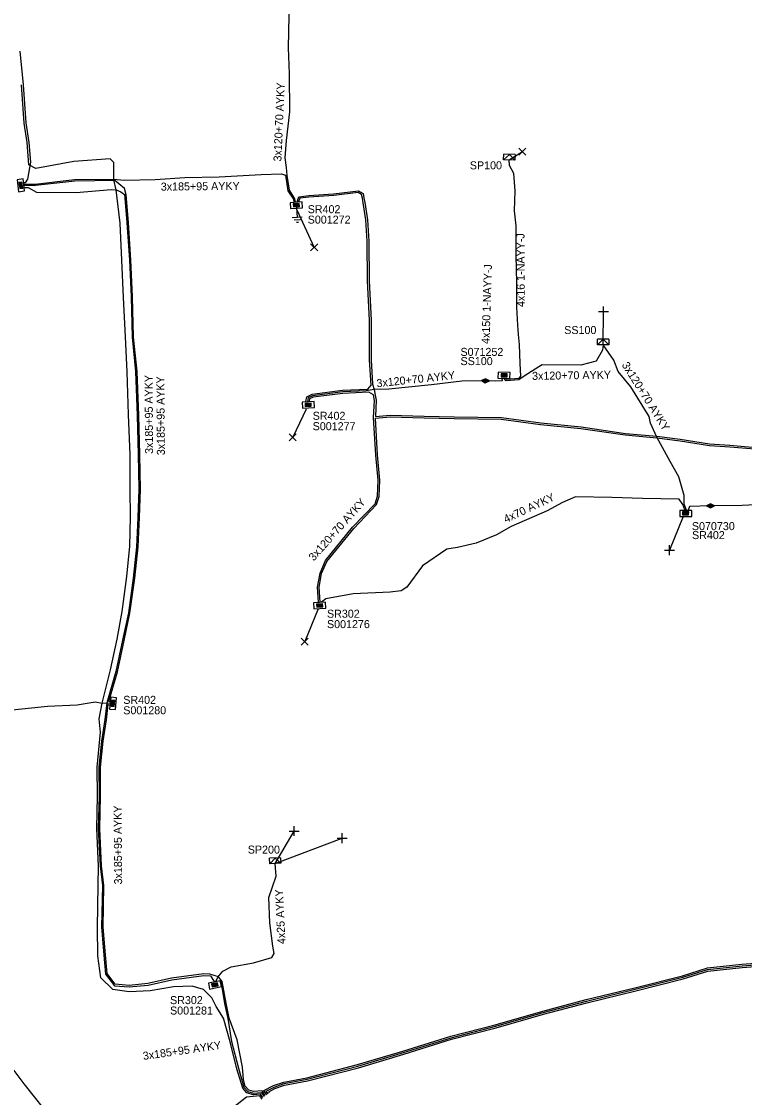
# Model space of a CAD drawing. Extents: x -763093 to -760976, y -1155572 to -1152009.
# Drawn here: x -762630 to -762539.8, y -1154689.2 to -1154554.8 of the extents above; entities that cross this region are included whole.
import ezdxf

# ---------------------------------------------------------------- set-up
doc = ezdxf.new("R2010")
doc.units = 0
for name, color, linetype in [('Vrstva 1', 7, 'Continuous'), ('Vrstva 14', 7, 'Continuous'), ('Vrstva 15', 7, 'Continuous'), ('Vrstva 19', 7, 'Continuous'), ('Vrstva 28', 7, 'Continuous'), ('Vrstva 29', 7, 'Continuous'), ('Vrstva 30', 7, 'Continuous'), ('Vrstva 31', 7, 'Continuous'), ('Vrstva 33', 7, 'Continuous'), ('Vrstva 34', 7, 'Continuous'), ('Vrstva 4', 7, 'Continuous'), ('Vrstva 5', 7, 'Continuous'), ('Vrstva 52', 7, 'Continuous'), ('Vrstva 54', 7, 'Continuous'), ('Vrstva 59', 7, 'Continuous'), ('Vrstva 6', 7, 'Continuous'), ('Vrstva 8', 7, 'Continuous'), ('Vrstva 9', 7, 'Continuous')]:
    doc.layers.add(name, color=color, linetype=linetype)

# ---------------------------------------------------------------- blocks, each defined once
blk = doc.blocks.new('NN870')
at = {"layer": 'Vrstva 4'}
for points in [[(0, -0.25), (0.5, 0), (0, 0.25), (-0.5, 0), (0, -0.25)], [(0.37, 0), (0, 0.19), (-0.36, 0), (0, -0.19), (0.37, 0)], [(0.24, 0), (0, 0.12), (-0.25, 0), (0, -0.12), (0.24, 0)], [(0.12, 0), (0, 0.06), (-0.13, 0), (0, -0.06), (0.12, 0)]]:
    blk.add_lwpolyline(points, dxfattribs=at)
blk = doc.blocks.new('NN800')
at = {"layer": 'Vrstva 1'}
for points in [[(-0.44, 0.44), (0.44, -0.44)], [(-0.44, -0.44), (0.44, 0.44)]]:
    blk.add_lwpolyline(points, dxfattribs=at)
blk = doc.blocks.new('NN620')
at = {"layer": 'Vrstva 8'}
for points in [[(0.75, 0), (-0.75, 0)], [(-0.75, 0), (-0.75, -0.75)], [(0.75, -0.75), (0.75, 0)], [(-0.75, -0.75), (0.75, -0.75)], [(0.37, -0.18), (-0.38, -0.18)], [(-0.38, -0.18), (-0.38, -0.56)], [(-0.38, -0.56), (0.37, -0.56)], [(0.32, -0.23), (-0.33, -0.23)], [(-0.33, -0.23), (-0.33, -0.51)], [(-0.33, -0.51), (0.32, -0.51)], [(0.27, -0.27), (-0.28, -0.27)], [(-0.28, -0.27), (-0.28, -0.46)], [(-0.28, -0.46), (0.27, -0.46)], [(0.23, -0.32), (-0.23, -0.32)], [(-0.23, -0.32), (-0.23, -0.42)], [(-0.23, -0.42), (0.23, -0.42)], [(-0.19, -0.37), (0.19, -0.37)], [(0.23, -0.42), (0.23, -0.32)], [(0.27, -0.46), (0.27, -0.27)], [(0.32, -0.51), (0.32, -0.23)], [(0.37, -0.56), (0.37, -0.18)]]:
    blk.add_lwpolyline(points, dxfattribs=at)
blk = doc.blocks.new('NN630')
at = {"layer": 'Vrstva 9'}
for points in [[(0, -0.7), (-0.7, 0)], [(-0.7, -0.7), (-0.7, 0), (0.7, 0), (0.7, -0.7)], [(-0.7, -0.7), (0.7, -0.7)], [(0, -0.7), (0.7, 0)]]:
    blk.add_lwpolyline(points, dxfattribs=at)
blk = doc.blocks.new('NN810')
at = {"layer": 'Vrstva 14'}
for points in [[(0, -0.64), (0, -1.89)], [(0.63, -1.89), (-0.62, -1.89)], [(0.39, -2.2), (-0.4, -2.2)], [(0, -2.52), (-0.12, -2.52)], [(0.14, -2.52), (0, -2.52)]]:
    blk.add_lwpolyline(points, dxfattribs=at)

msp = doc.modelspace()

# ---------------------------------------------------------------- linework, layer by layer
at = {"layer": 'Vrstva 5'}
for points in [[(-762595.83, -1154577.36), (-762595.94, -1154576.91), (-762596.59, -1154575.89), (-762596.86, -1154574.08), (-762596.96, -1154573.09), (-762597.12, -1154571.85), (-762596.95, -1154569.71), (-762596.52, -1154566.13), (-762596.58, -1154561.37), (-762596.7, -1154558.13), (-762596.63, -1154554.1), (-762596.69, -1154552.42), (-762596.12, -1154549.48), (-762594.77, -1154547.62), (-762592.4, -1154546.5)], [(-762630.26, -1154558.56), (-762629.86, -1154562.74), (-762629.51, -1154567.5), (-762629.15, -1154569.95), (-762628.94, -1154572.41), (-762629.3, -1154574.53), (-762629.59, -1154574.98), (-762629.73, -1154574.99)], [(-762599.91, -1154689.21), (-762600.2, -1154688.79), (-762601.1, -1154688.88), (-762601.89, -1154688.63), (-762602.42, -1154688.05), (-762603.16, -1154685.63), (-762604.01, -1154682.26), (-762604.82, -1154679.31), (-762605.75, -1154677.86), (-762606.27, -1154676.79), (-762607.3, -1154675.75), (-762608.73, -1154675.33), (-762611.06, -1154675.42), (-762613.97, -1154675.92), (-762616.61, -1154676.03), (-762618.64, -1154675.73), (-762620.16, -1154674.27), (-762620.52, -1154671.52), (-762620.55, -1154667.97), (-762620.48, -1154662.72), (-762620.44, -1154660.31), (-762620.66, -1154655.62), (-762620.57, -1154651.6), (-762620.6, -1154647.96), (-762620.19, -1154643.58), (-762620.36, -1154641.94), (-762619.96, -1154639.97), (-762618.92, -1154635.82), (-762618.12, -1154631.96), (-762617.49, -1154628.54), (-762616.9, -1154624.17), (-762616.53, -1154620.36), (-762616.44, -1154616.74), (-762616.48, -1154613.25), (-762616.49, -1154608.94), (-762616.67, -1154603.92), (-762616.84, -1154598.6), (-762617.06, -1154594.22), (-762617.31, -1154589.29), (-762617.51, -1154584.64), (-762617.73, -1154580.02), (-762618.22, -1154575.86), (-762618.51, -1154574.61), (-762618.53, -1154572.44), (-762618.97, -1154571.99), (-762623.51, -1154572.32), (-762628.25, -1154573.21), (-762629.12, -1154572.75), (-762629.35, -1154569.97), (-762629.71, -1154567.52), (-762630.06, -1154562.76)], [(-762629.72, -1154575.15), (-762628.34, -1154575.14), (-762623.41, -1154574.57), (-762618.51, -1154574.51), (-762617.23, -1154574.66), (-762613.36, -1154574.56), (-762609.67, -1154574.33), (-762605.36, -1154574.24), (-762600.12, -1154573.96), (-762597.57, -1154573.86), (-762597.07, -1154574.05), (-762596.79, -1154575.97), (-762596.1, -1154577.01), (-762596.03, -1154577.39)], [(-762619, -1154639.76), (-762619.14, -1154639.76), (-762618.08, -1154636.04), (-762617.23, -1154632.15), (-762616.5, -1154628.72), (-762615.91, -1154624.38), (-762615.5, -1154620.45), (-762615.32, -1154616.78), (-762615.2, -1154613.24), (-762615.29, -1154608.92), (-762615.4, -1154604.04), (-762615.62, -1154598.55), (-762616.06, -1154594.25), (-762616.17, -1154589.22), (-762616.38, -1154584.61), (-762616.69, -1154579.94), (-762616.96, -1154576.49), (-762617.19, -1154575.69), (-762617.88, -1154575.1), (-762618.38, -1154574.71), (-762623.39, -1154574.77), (-762628.32, -1154575.34), (-762629.7, -1154575.35)], [(-762629.67, -1154575.55), (-762629.21, -1154575.56), (-762628.18, -1154576.15), (-762623.22, -1154576.18), (-762618.86, -1154575.8), (-762618.22, -1154575.86), (-762617.64, -1154576.12), (-762617.17, -1154576.43), (-762616.89, -1154579.96), (-762616.58, -1154584.63), (-762616.37, -1154589.22), (-762616.23, -1154594.25), (-762615.82, -1154598.57), (-762615.6, -1154604.04), (-762615.49, -1154608.92), (-762615.4, -1154613.24), (-762615.52, -1154616.78), (-762615.67, -1154620.45), (-762616.11, -1154624.36), (-762616.7, -1154628.68), (-762617.43, -1154632.11), (-762618.28, -1154636), (-762619.4, -1154639.94), (-762619.65, -1154642.01), (-762620.07, -1154644.7), (-762620.4, -1154647.97), (-762620.37, -1154651.6), (-762620.46, -1154655.62), (-762620.24, -1154660.3), (-762619.95, -1154662.75), (-762620.06, -1154667.93), (-762619.75, -1154671.43), (-762619.57, -1154673.82), (-762618.45, -1154675.28), (-762616.59, -1154675.42), (-762614.22, -1154675.2), (-762611.28, -1154674.51), (-762607.29, -1154673.97), (-762606.45, -1154674.04), (-762606, -1154674.72)], [(-762595.64, -1154577.36), (-762595.43, -1154576.74), (-762594.18, -1154576.57), (-762591.08, -1154576.37), (-762587.97, -1154576), (-762587.4, -1154576.3), (-762587.28, -1154576.88), (-762587.17, -1154577.46), (-762586.85, -1154579.59), (-762586.68, -1154582.29), (-762586.62, -1154587.23), (-762586.39, -1154592.12), (-762586.4, -1154597.09), (-762586.2, -1154600.12), (-762586.02, -1154600.78), (-762585.88, -1154601.49), (-762585.76, -1154602.14), (-762585.86, -1154604.18), (-762584.02, -1154604.01), (-762579.76, -1154604.13), (-762576.01, -1154604.2), (-762570.12, -1154604.3), (-762565.21, -1154604.96), (-762560.16, -1154605.48), (-762554.63, -1154606.28), (-762550.7, -1154606.64), (-762547.79, -1154607.02), (-762544.13, -1154607.59), (-762541.57, -1154607.77), (-762537.41, -1154608.11)], [(-762594.53, -1154602.29), (-762594.43, -1154601.71), (-762593.76, -1154601.38), (-762589.95, -1154600.89), (-762586.81, -1154600.74), (-762586.39, -1154600.24), (-762586.6, -1154597.09), (-762586.59, -1154592.12), (-762586.82, -1154587.23), (-762586.88, -1154582.29), (-762587.05, -1154579.61), (-762587.37, -1154577.5), (-762587.48, -1154576.92), (-762587.58, -1154576.44), (-762588.01, -1154576.2), (-762591.06, -1154576.57), (-762594.16, -1154576.77), (-762595.31, -1154576.92), (-762595.45, -1154577.36)], [(-762547.01, -1154615.87), (-762547.28, -1154615.11), (-762547.31, -1154614.03), (-762547.97, -1154611.72), (-762549.05, -1154609.79), (-762550.71, -1154606.74), (-762551.49, -1154604.99), (-762551.66, -1154604.16), (-762553.97, -1154600.48), (-762555.54, -1154598.55), (-762556.07, -1154597.15), (-762557.41, -1154595.22), (-762557.51, -1154595.87), (-762558.3, -1154597.26), (-762560.2, -1154597.77), (-762565.03, -1154597.72), (-762565.44, -1154597.96), (-762567.26, -1154599.13), (-762567.92, -1154599.57), (-762569.53, -1154599.72), (-762569.79, -1154599.41)], [(-762572.12, -1154599.71), (-762575.05, -1154599.77), (-762578.86, -1154600.22), (-762584.19, -1154600.75), (-762586.02, -1154600.78), (-762586.99, -1154600.95), (-762589.93, -1154601.09), (-762593.7, -1154601.57), (-762594.25, -1154601.84), (-762594.33, -1154602.29)], [(-762570.07, -1154599.41), (-762570.03, -1154599.7), (-762570.81, -1154599.75), (-762572.12, -1154599.71)], [(-762592.94, -1154627.35), (-762593.07, -1154625.48), (-762592.77, -1154623.72), (-762592.08, -1154622.17), (-762588.7, -1154618), (-762585.9, -1154615.06), (-762585.58, -1154614.12), (-762585.51, -1154612.14), (-762585.8, -1154608.98), (-762586.07, -1154604.29), (-762585.96, -1154602.16), (-762586.09, -1154601.45), (-762586.66, -1154601.13), (-762589.91, -1154601.29), (-762593.64, -1154601.76), (-762594.07, -1154601.97), (-762594.12, -1154602.28)], [(-762592.74, -1154627.35), (-762592.87, -1154625.5), (-762592.57, -1154623.78), (-762591.9, -1154622.27), (-762588.54, -1154618.14), (-762585.72, -1154615.16), (-762585.38, -1154614.16), (-762585.31, -1154612.14), (-762585.6, -1154608.96), (-762585.86, -1154604.38), (-762584.02, -1154604.21), (-762579.76, -1154604.33), (-762576.01, -1154604.4), (-762570.14, -1154604.5), (-762565.23, -1154605.16), (-762560.18, -1154605.68), (-762554.65, -1154606.48), (-762550.72, -1154606.84), (-762547.81, -1154607.22), (-762544.15, -1154607.79), (-762541.59, -1154607.97), (-762537.43, -1154608.31)], [(-762547.23, -1154615.84), (-762547.46, -1154615.17), (-762547.9, -1154614.48), (-762552.51, -1154614.4), (-762556.31, -1154614.29), (-762560.87, -1154614.2), (-762562.5, -1154614.91), (-762564.4, -1154615.97), (-762568.88, -1154617.9), (-762570.75, -1154618.94), (-762573.27, -1154620), (-762575.62, -1154620.55), (-762576.95, -1154620.74), (-762579.96, -1154622.84), (-762581.91, -1154625.49), (-762582.62, -1154625.96), (-762584, -1154626.11), (-762588.65, -1154626.31), (-762592.06, -1154626.93), (-762592.59, -1154627.34)], [(-762503.87, -1154616.15), (-762504.09, -1154615.27), (-762506.42, -1154615.21), (-762510.1, -1154615.29), (-762514.01, -1154615.2), (-762517.37, -1154615.23), (-762522.56, -1154615.41), (-762527.8, -1154615.36), (-762531.54, -1154615.29), (-762535.89, -1154615.07), (-762540.05, -1154615.28), (-762544.02, -1154615.34), (-762546.63, -1154615.39), (-762546.79, -1154615.85)], [(-762632.02, -1154640.87), (-762626.81, -1154640.36), (-762623.09, -1154640.17), (-762620.87, -1154639.79), (-762619.96, -1154639.97), (-762619.3, -1154639.95), (-762619.02, -1154639.96)], [(-762599.6, -1154688.97), (-762600.01, -1154688.37), (-762601.06, -1154688.48), (-762601.67, -1154688.29), (-762602.12, -1154687.79), (-762602.34, -1154686.96), (-762602.43, -1154685.45), (-762603.13, -1154682.02), (-762604.1, -1154679.3), (-762604.48, -1154677.46), (-762604.97, -1154674.72), (-762605.46, -1154674.14), (-762606.51, -1154673.83), (-762607.29, -1154673.77), (-762611.32, -1154674.31), (-762614.26, -1154675), (-762616.59, -1154675.22), (-762618.35, -1154675.08), (-762619.37, -1154673.74), (-762619.55, -1154671.41), (-762619.86, -1154667.93), (-762619.75, -1154662.73), (-762620.04, -1154660.29), (-762620.26, -1154655.62), (-762620.17, -1154651.6), (-762620.2, -1154647.98), (-762619.87, -1154644.72), (-762619.45, -1154642.05), (-762619.22, -1154640.15), (-762619.05, -1154640.16)], [(-762605.77, -1154674.72), (-762605.54, -1154674.21), (-762604.91, -1154673.43), (-762603.88, -1154672.91), (-762601.07, -1154672.39), (-762598.79, -1154671.73), (-762598.51, -1154671.25), (-762598.66, -1154670.34), (-762599.02, -1154667.4), (-762599.15, -1154664.25), (-762598.26, -1154661.59), (-762598.35, -1154660.01)], [(-762599.42, -1154688.87), (-762599.77, -1154688.36), (-762598.56, -1154687.74), (-762597.3, -1154687.29), (-762594.4, -1154686.75), (-762588.08, -1154685.12), (-762582.41, -1154683.42), (-762576.45, -1154681.57), (-762570.88, -1154680.13), (-762564.94, -1154678.42), (-762559.54, -1154677), (-762553.45, -1154675.51), (-762547.51, -1154674.02), (-762544.4, -1154673.04), (-762540.08, -1154672.59), (-762537.32, -1154672.36)], [(-762599.25, -1154688.76), (-762599.48, -1154688.43), (-762598.48, -1154687.92), (-762597.25, -1154687.48), (-762594.36, -1154686.95), (-762588.03, -1154685.31), (-762582.35, -1154683.61), (-762576.4, -1154681.76), (-762570.83, -1154680.32), (-762564.89, -1154678.61), (-762559.49, -1154677.19), (-762553.4, -1154675.7), (-762547.46, -1154674.21), (-762544.36, -1154673.24), (-762540.06, -1154672.79), (-762537.31, -1154672.56)], [(-762599.09, -1154688.65), (-762599.18, -1154688.51), (-762598.4, -1154688.1), (-762597.2, -1154687.67), (-762594.32, -1154687.15), (-762587.98, -1154685.5), (-762582.29, -1154683.8), (-762576.35, -1154681.95), (-762570.78, -1154680.51), (-762564.84, -1154678.8), (-762559.44, -1154677.38), (-762553.35, -1154675.89), (-762547.41, -1154674.4), (-762544.32, -1154673.44), (-762540.04, -1154672.99), (-762537.3, -1154672.76)], [(-762605.2, -1154674.74), (-762605.04, -1154675.43), (-762604.68, -1154677.5), (-762604.3, -1154679.34), (-762603.81, -1154682.22), (-762602.96, -1154685.57), (-762602.27, -1154687.92), (-762601.78, -1154688.46), (-762601.08, -1154688.68), (-762600.1, -1154688.58), (-762599.75, -1154689.1)], [(-762612.11, -1154709.48), (-762611.94, -1154709.23), (-762614.1, -1154706.59), (-762617.47, -1154702.57), (-762620.54, -1154698.81), (-762623.38, -1154695.38), (-762626.02, -1154692.18), (-762629.71, -1154687.53), (-762632.2, -1154684.19), (-762632.47, -1154683.46), (-762633.17, -1154682.96), (-762634.25, -1154682.74), (-762636.36, -1154682.22), (-762638.73, -1154681.94), (-762640.94, -1154682.27), (-762641.85, -1154683.11), (-762646.08, -1154687.29), (-762650.37, -1154691.71), (-762658.67, -1154700.2), (-762662.43, -1154704.09), (-762662.44, -1154704.48)], [(-762600.01, -1154689.43), (-762600.29, -1154689.02), (-762601.94, -1154689.18), (-762603.69, -1154690.57), (-762605.48, -1154692.23), (-762606.63, -1154693.35), (-762607.22, -1154694.34), (-762607.4, -1154695.63), (-762605.57, -1154698.11), (-762603.01, -1154701.39), (-762602.47, -1154702.23), (-762602.69, -1154702.73), (-762603.93, -1154703.61), (-762606.85, -1154706.27), (-762609.5, -1154708.51), (-762610.55, -1154709.38), (-762611.52, -1154709.64), (-762611.98, -1154709.63)]]:
    msp.add_lwpolyline(points, dxfattribs=at)
at = {"layer": 'Vrstva 52'}
msp.add_lwpolyline([(-762569.52, -1154599.42), (-762569.47, -1154599.52), (-762567.94, -1154599.37), (-762567.85, -1154599.36), (-762567.7, -1154599.13), (-762567.78, -1154597.53), (-762567.84, -1154595.16), (-762568, -1154593.92), (-762568.07, -1154592.75), (-762568.2, -1154590.5), (-762568.21, -1154587.46), (-762568.27, -1154584.01), (-762568.27, -1154580.37), (-762568.49, -1154578.47), (-762568.38, -1154576), (-762568.56, -1154573.81), (-762569.12, -1154572.83), (-762569.14, -1154572.13)], dxfattribs=at)
at = {"layer": 'Vrstva 59'}
for points in [[(-762569.14, -1154572.13), (-762567.5, -1154571.08)], [(-762595.67, -1154578.36), (-762593.5, -1154583.06)], [(-762557.41, -1154595.22), (-762557.38, -1154591.06)], [(-762594.51, -1154603.24), (-762596.18, -1154606.77)], [(-762547.41, -1154616.66), (-762549.13, -1154620.88)], [(-762593.02, -1154628.21), (-762594.67, -1154632.29)], [(-762598.35, -1154660.01), (-762595.98, -1154655.94)], [(-762598.35, -1154660.01), (-762590.01, -1154656.82)]]:
    msp.add_lwpolyline(points, dxfattribs=at)

# ---------------------------------------------------------------- block references
at = {"layer": 'Vrstva 15', "rotation": 3.353702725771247}
msp.add_blockref('NN810', (-762595.74, -1154577.42), dxfattribs=at)
at = {"layer": 'Vrstva 19'}
for p, rotation in [((-762572.12, -1154599.71), -1.8591754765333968), ((-762544.02, -1154615.34), 180)]:
    msp.add_blockref('NN870', p, dxfattribs=dict(at, rotation=rotation))
at = {"layer": 'Vrstva 28'}
for p, rotation in [((-762629.76, -1154575.25), -82.48521749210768), ((-762595.74, -1154577.42), 3.353702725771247), ((-762569.8, -1154599.4), 178.6205321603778), ((-762594.26, -1154602.34), 3.0306583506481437), ((-762547.1, -1154615.9), -0.18542220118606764), ((-762592.84, -1154627.4), 3.4068194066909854), ((-762618.99, -1154639.96), 84.04512737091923), ((-762605.97, -1154674.79), 11.640948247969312)]:
    msp.add_blockref('NN620', p, dxfattribs=dict(at, rotation=rotation))
at = {"layer": 'Vrstva 31'}
for p, rotation in [((-762569.14, -1154572.13), 178.04432317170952), ((-762557.41, -1154595.22), 179.78818606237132), ((-762598.35, -1154660.01), -177.0891610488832)]:
    msp.add_blockref('NN630', p, dxfattribs=dict(at, rotation=rotation))
at = {"layer": 'Vrstva 34'}
for p in [(-762567.5, -1154571.08), (-762593.5, -1154583.06), (-762596.18, -1154606.77), (-762594.67, -1154632.29)]:
    msp.add_blockref('NN800', p, dxfattribs=at)
for p, rotation in [((-762557.38, -1154591.06), 45), ((-762549.13, -1154620.88), 45), ((-762595.98, -1154655.94), 45.00000009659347), ((-762590.01, -1154656.82), 45)]:
    msp.add_blockref('NN800', p, dxfattribs=dict(at, rotation=rotation))

# ---------------------------------------------------------------- texts
at = {"layer": 'Vrstva 29'}
for s, p in [('S001272', (-762594.31, -1154580.08)), ('S071252', (-762575.23, -1154596.6)), ('S001277', (-762593.69, -1154605.88)), ('S070730', (-762546.33, -1154618.36)), ('S001276', (-762591.9, -1154630.6)), ('S001280', (-762617.34, -1154641.36)), ('S001281', (-762611.5, -1154678.86))]:
    msp.add_text(s, height=1, dxfattribs=at).set_placement(p)
at = {"layer": 'Vrstva 30'}
for s, p in [('SR402', (-762594.31, -1154578.78)), ('SS100', (-762575.22, -1154597.75)), ('SR402', (-762593.69, -1154604.58)), ('SR402', (-762546.31, -1154619.48)), ('SR302', (-762591.9, -1154629.3)), ('SR402', (-762617.34, -1154640.06)), ('SR302', (-762611.5, -1154677.56))]:
    msp.add_text(s, height=1, dxfattribs=at).set_placement(p)
at = {"layer": 'Vrstva 33'}
for s, p in [('SP100', (-762574.06, -1154573.3)), ('SS100', (-762562.27, -1154593.87)), ('SP200', (-762601.79, -1154658.76))]:
    msp.add_text(s, height=1, dxfattribs=at).set_placement(p)
at = {"layer": 'Vrstva 54'}
msp.add_text('4x16 1-NAYY-J', height=1, rotation=90.188, dxfattribs=at).set_placement((-762567.2, -1154590.5))
at = {"layer": 'Vrstva 6'}
for s, rotation, p in [('3x120+70 AYKY', 87.46, (-762597.6, -1154572.34)), ('3x185+95 AYKY', 0.53, (-762612.65, -1154575.96)), ('4x150 1-NAYY-J', 88.251, (-762571.6, -1154595.12)), ('3x120+70 AYKY', 0.855, (-762566.28, -1154599.6)), ('3x120+70 AYKY', 302.185, (-762555.13, -1154597.73)), ('3x185+95 AYKY', 90.302, (-762613.62, -1154608.84)), ('3x185+95 AYKY', 90.36, (-762612.14, -1154609)), ('3x120+70 AYKY', 6.135, (-762585.66, -1154600.53)), ('3x120+70 AYKY', 48.289, (-762593.55, -1154622.29)), ('4x70 AYKY', 25.228, (-762569.55, -1154617.5)), ('3x185+95 AYKY', 90.361, (-762617.48, -1154662.61)), ('4x25 AYKY', 92.655, (-762597.08, -1154670.04)), ('3x185+95 AYKY', 8.099, (-762614.82, -1154684.54))]:
    msp.add_text(s, height=1, rotation=rotation, dxfattribs=at).set_placement(p)

doc.saveas('drawing.dxf')
